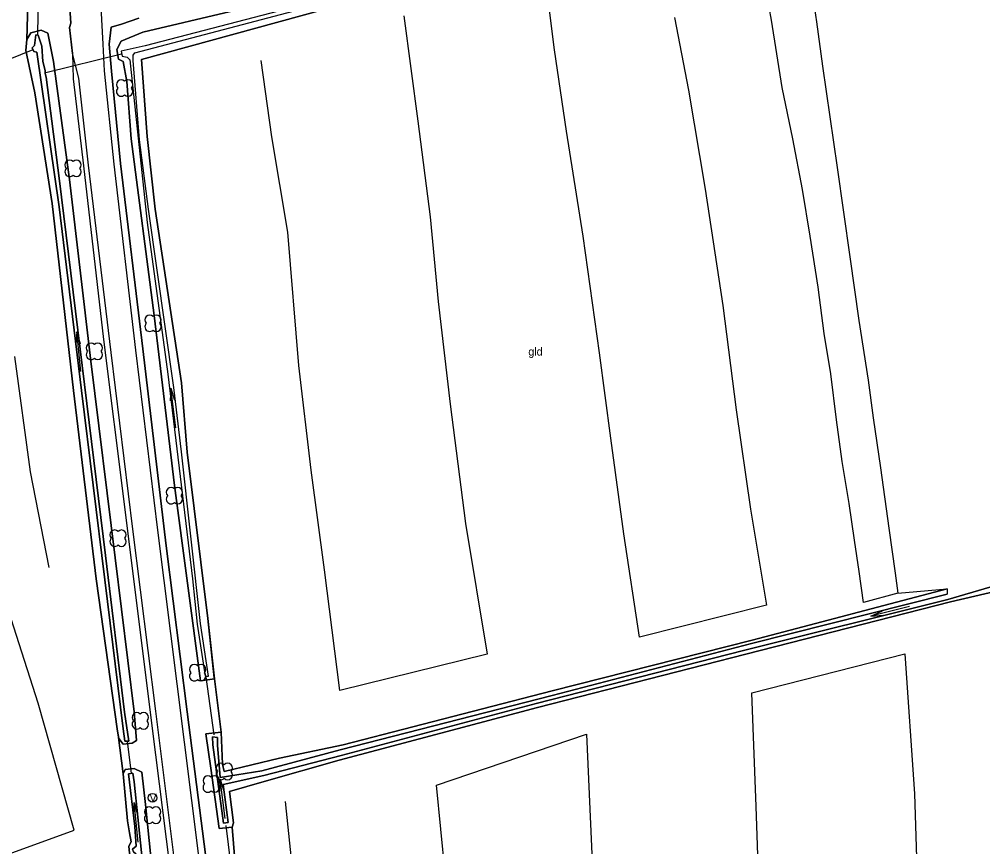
# Model space of a CAD drawing. Extents: x 154825 to 158680, y 370717 to 378075.
# Drawn here: x 157272.6 to 157393.1, y 372826 to 372929.4 of the extents above; entities that cross this region are included whole.
import ezdxf

# ---------------------------------------------------------------- set-up
doc = ezdxf.new("R2010")
doc.units = 0
for name, color, linetype in [('boom', 7, 'Continuous'), ('cultuurscheiding', 7, 'Continuous'), ('duiker lijn', 7, 'Continuous'), ('grasland_productiegrasl(vs)', 7, 'Continuous'), ('greppel - midden sloot', 7, 'Continuous'), ('hoogteverschillijn', 7, 'Continuous'), ('insteek sloot', 7, 'Continuous'), ('kant gesloten verharding', 7, 'Continuous'), ('kant onverhard', 7, 'Continuous'), ('Sloot bodem', 7, 'Continuous'), ('stroomrichting  watergangen', 7, 'Continuous'), ('verkeersbord', 7, 'Continuous'), ('vlak_Grasland', 7, 'Continuous'), ('vlak_Grazige_vegetatie', 7, 'Continuous')]:
    doc.layers.add(name, color=color, linetype=linetype)

msp = doc.modelspace()

# ---------------------------------------------------------------- linework, layer by layer
at = {"layer": 'boom'}
for centre, start, end in [((157285.38, 372921.25), 45, 225), ((157286.23, 372921.25), 315, 135), ((157285.38, 372920.4), 134.7431, 315), ((157286.23, 372920.4), 225, 45), ((157278.95, 372911.22), 45, 225), ((157279.8, 372911.22), 315, 135), ((157278.95, 372910.37), 134.7431, 315), ((157279.8, 372910.37), 225, 45), ((157288.94, 372891.86), 45, 225), ((157289.79, 372891.86), 315, 135), ((157288.94, 372891.01), 134.7431, 315), ((157289.79, 372891.01), 225, 45), ((157281.61, 372888.35), 45, 225), ((157282.46, 372888.35), 315, 135), ((157281.61, 372887.5), 134.7431, 315), ((157282.46, 372887.5), 225, 45), ((157291.62, 372870.3), 45, 225), ((157292.46, 372870.3), 315, 135), ((157291.62, 372869.45), 134.7431, 315), ((157292.46, 372869.45), 225, 45), ((157284.57, 372864.99), 45, 225), ((157285.42, 372864.99), 315, 135), ((157284.57, 372864.14), 134.7431, 315), ((157285.42, 372864.14), 225, 45), ((157294.52, 372848.17), 45, 225), ((157295.36, 372848.17), 315, 135), ((157294.52, 372847.33), 134.7431, 315), ((157295.36, 372847.33), 225, 45), ((157287.34, 372842.16), 45, 225), ((157288.19, 372842.16), 315, 135), ((157287.34, 372841.31), 134.7431, 315), ((157288.19, 372841.31), 225, 45), ((157297.84, 372835.83), 45, 225), ((157298.69, 372835.83), 315, 135), ((157296.21, 372834.26), 45, 225), ((157297.06, 372834.26), 315, 135), ((157297.84, 372834.98), 134.7431, 315), ((157298.69, 372834.98), 225, 45), ((157296.21, 372833.41), 134.7431, 315), ((157297.06, 372833.41), 225, 45), ((157288.88, 372830.37), 45, 225), ((157289.73, 372830.37), 315, 135), ((157288.88, 372829.52), 134.7431, 315), ((157289.73, 372829.52), 225, 45)]:
    msp.add_arc(centre, 0.6, start, end, dxfattribs=at)
at = {"layer": 'cultuurscheiding'}
for points in [[(157273.57, 372926.89), (157273.75, 372932.84)], [(157297.01, 372847.1), (157297.87, 372840.32)], [(157285, 372839.98), (157285.61, 372835.12)], [(157299.27, 372828.45), (157299.79, 372821.84)]]:
    msp.add_lwpolyline(points, dxfattribs=at)
at = {"layer": 'duiker lijn'}
for points in [[(157275.02, 372932.59), (157274.91, 372927.48)], [(157274.34, 372925.61), (157269.46, 372923.65)], [(157285.43, 372925.08), (157275.97, 372922.72)], [(157297, 372840), (157296, 372847.25)], [(157286.11, 372839.14), (157286.62, 372835.21)], [(157298.47, 372828.67), (157299.35, 372821.52)]]:
    msp.add_lwpolyline(points, dxfattribs=at)
at = {"layer": 'greppel - midden sloot'}
for points in [[(157318.67, 372934.04), (157288.4, 372926.09), (157285.36, 372925.43), (157285.52, 372924.8), (157286.11, 372924.7), (157286.47, 372924.34), (157286.84, 372920.82), (157288.65, 372904.01), (157291.2, 372885.05), (157294.29, 372859.48), (157294.89, 372853.8), (157295.87, 372847.3), (157296.29, 372847.31), (157295.28, 372853.91), (157292.92, 372875.35), (157291.97, 372883.39), (157288.79, 372905.69), (157287.69, 372914.37), (157286.86, 372924.28), (157286.9, 372924.96), (157287.1, 372925.24), (157310.82, 372931.47)], [(157274.86, 372925.32), (157274.46, 372925.39), (157274.24, 372925.84), (157274.53, 372926.13), (157274.71, 372927.47), (157275.01, 372927.46), (157275.48, 372926.07), (157275.59, 372924.13), (157275.88, 372923.03), (157275.9, 372922.65), (157276.01, 372922.19), (157277.63, 372909.55), (157283.42, 372862.39), (157285.8, 372842.83), (157286.35, 372839.19), (157285.85, 372839.19), (157285.64, 372840.74), (157283.35, 372859.37), (157280.43, 372883.02), (157277.62, 372906), (157274.86, 372925.32)], [(157388.72, 372856.91), (157363.17, 372850.53), (157337.25, 372843.92), (157312.87, 372837.42), (157303.23, 372834.9), (157298.14, 372833.77), (157298.77, 372829.04), (157298.18, 372828.95), (157296.85, 372838.73), (157296.8, 372839.73), (157297.43, 372839.66), (157297.42, 372838.68), (157297.76, 372834.65), (157302.98, 372835.5), (157312.76, 372838.12), (157339.24, 372844.92), (157364.15, 372851.4), (157388.64, 372857.57)], [(157286.3, 372835.11), (157286.85, 372835.2), (157287.01, 372834.13), (157287.93, 372825.29), (157288.09, 372824.09), (157287.66, 372823.94), (157287.28, 372824.13), (157287.23, 372825.12), (157286.94, 372825.35), (157286.8, 372825.7), (157287.24, 372826.06), (157287.08, 372828.51), (157286.3, 372835.11)]]:
    msp.add_lwpolyline(points, dxfattribs=at)
at = {"layer": 'hoogteverschillijn'}
for points in [[(157371.93, 372931.61), (157372.29, 372929.12), (157373.03, 372923.58), (157374.86, 372910.92), (157376.47, 372899.72), (157377.58, 372891.79), (157378.73, 372884.31), (157379.38, 372879.62), (157380.3, 372873.36), (157381.34, 372865.81), (157382.1, 372860.19), (157382.45, 372857.7), (157378.17, 372856.53), (157377.61, 372860.4), (157377.03, 372864.32), (157376.35, 372868.9), (157375.49, 372874.16), (157374.79, 372879.35), (157374.06, 372885.12), (157373.24, 372890.16), (157372.49, 372895.93), (157371.5, 372902.31), (157370.55, 372908.16), (157369.32, 372914.48), (157368, 372920.92), (157366.67, 372929.3), (157365.48, 372935.71)], [(157354.53, 372929.67), (157356.27, 372920.58), (157358.36, 372908.18), (157360.59, 372893.66), (157362.26, 372880.61), (157364.02, 372868.18), (157366.02, 372856.2), (157350.16, 372852.18), (157348.21, 372865.09), (157346.59, 372877.06), (157345.15, 372887.75), (157343.12, 372902.33), (157341.04, 372915.45), (157339.54, 372925.59), (157338.48, 372933.93)], [(157320.72, 372929.86), (157322.45, 372916.71), (157324, 372904.73), (157325.01, 372894.15), (157326.49, 372881.32), (157328.43, 372866.4), (157331.11, 372850.09), (157312.73, 372845.54), (157310.8, 372860.62), (157309.11, 372873.05), (157307.58, 372886.17), (157306.2, 372902.83), (157304.21, 372914.75), (157302.88, 372924.29)], [(157272.04, 372887.26), (157274, 372872.86), (157276.34, 372860.9)], [(157264.46, 372822.6), (157279.52, 372828.06), (157275, 372843.96), (157269.55, 372860.88)], [(157365.36, 372812.84), (157364.74, 372831.03), (157364.21, 372845.23), (157383.32, 372850.1), (157384.54, 372832.62), (157385.08, 372815.35)], [(157326.96, 372811.68), (157324.79, 372833.68), (157343.55, 372840.05), (157344.51, 372818.54)], [(157305.88, 372831.65), (157306.82, 372822.45)]]:
    msp.add_lwpolyline(points, dxfattribs=at)
at = {"layer": 'insteek sloot'}
for points in [[(157297.04, 372846.99), (157295.31, 372846.72), (157292.04, 372871.14), (157289.51, 372892.39), (157286.62, 372914.5), (157286.1, 372921.67), (157285.63, 372924.14), (157285.03, 372924.45), (157284.84, 372925.67), (157285.38, 372926.7), (157288.07, 372927.8), (157299.03, 372930.41), (157319.21, 372935.81), (157344.59, 372941.96), (157372.7, 372949.2)], [(157297.01, 372847.1), (157296.22, 372854.54), (157293.65, 372875.31), (157292.94, 372883.99), (157289.64, 372905.7), (157288.62, 372914.78), (157287.91, 372924.41), (157310.87, 372930.69), (157339.38, 372937.6), (157365.45, 372944.04), (157374.71, 372946.41)], [(157274.61, 372920.24), (157273.45, 372925.52), (157273.57, 372926.89), (157274.07, 372927.74), (157275.38, 372928.06), (157276.2, 372927.68), (157276.94, 372924.16), (157278.93, 372909.42), (157281.58, 372886.68), (157284.64, 372862.12), (157287, 372842.87), (157287.29, 372839.29), (157286.75, 372838.96), (157285.61, 372838.82), (157285.08, 372839.53), (157284.93, 372840.43), (157282.25, 372859.48), (157279.44, 372883.03), (157276.75, 372906.39), (157274.61, 372920.24)], [(157299.27, 372828.45), (157299.41, 372828.98), (157298.93, 372832.92), (157303.25, 372834.17), (157312.62, 372836.82), (157337.42, 372843.4), (157363.46, 372850.05), (157389.02, 372856.63), (157399.96, 372859.14)], [(157388.63, 372858.23), (157364.23, 372851.83), (157339.25, 372845.47), (157313.11, 372838.73), (157305.15, 372837.07), (157298.27, 372835.41), (157298.06, 372836.3), (157297.87, 372840.32), (157295.97, 372840.13), (157296.6, 372835.82), (157297.64, 372828.27), (157299.27, 372828.45)], [(157286.18, 372829.25), (157285.61, 372835.12), (157285.89, 372835.64), (157286.99, 372835.79), (157287.96, 372835.34), (157288.43, 372831.26), (157289.07, 372824.74), (157288.72, 372823.74), (157287.71, 372823.42), (157286.81, 372823.92), (157286.43, 372825.18), (157286.35, 372826.05), (157286.62, 372826.63), (157286.43, 372827.72), (157286.18, 372829.25)]]:
    msp.add_lwpolyline(points, dxfattribs=at)
at = {"layer": 'kant gesloten verharding'}
for points in [[(157309.45, 372683.01), (157307.81, 372696.98), (157304.61, 372723.02), (157300.48, 372751.36), (157295.86, 372793.73), (157292.97, 372816.93), (157289.7, 372842.93), (157286.83, 372865.69), (157284.12, 372887.77), (157281.31, 372911.18), (157280.08, 372922.05), (157279.28, 372925.15), (157278.91, 372928.41), (157279.1, 372928.93), (157278.95, 372930.8), (157279.23, 372931.22), (157279.08, 372935.46), (157279.01, 372939.65), (157278.96, 372950.66), (157279.4, 372975.64), (157279.77, 372996.09), (157280.14, 373018.34), (157280.49, 373042.16), (157280.55, 373054.05)], [(157312.71, 372683.69), (157310.98, 372696.7), (157309.59, 372707.75), (157308.84, 372712.76), (157307.63, 372722.75), (157304.62, 372748.14), (157302.85, 372762.12), (157300.23, 372783.38), (157299.04, 372793.03), (157296.06, 372817.18), (157292.38, 372846.37), (157289.96, 372865.56), (157287.21, 372888.06), (157284.5, 372911.32), (157283.29, 372922.98), (157283.13, 372926.33), (157282.81, 372932.53)]]:
    msp.add_lwpolyline(points, dxfattribs=at)
at = {"layer": 'kant onverhard'}
for points in [[(157287.57, 372929.57), (157285.41, 372928.83), (157284.14, 372928.46), (157283.86, 372926.31), (157284.17, 372922.95), (157285.28, 372911.39), (157288.08, 372888.25), (157291.02, 372863.61), (157293.62, 372842.88), (157296.91, 372817.23), (157299.06, 372801.5), (157301.94, 372777.18), (157302.78, 372769.87), (157305.82, 372744.51), (157308.26, 372725.88), (157311.3, 372700.25), (157311.8, 372696.63), (157313.43, 372683.38), (157314.9, 372676.59), (157316.73, 372670.52), (157319.22, 372664.68)], [(157279.28, 372925.14), (157279.37, 372921.97), (157280.66, 372911.1), (157283.19, 372889.42), (157285.8, 372868.5), (157289.23, 372841.1), (157292.37, 372816.06), (157299.92, 372751.25), (157303.77, 372722.82), (157306.99, 372696.78), (157309.07, 372682.97), (157312.03, 372669.29), (157315.08, 372660.6)]]:
    msp.add_lwpolyline(points, dxfattribs=at)
at = {"layer": 'Sloot bodem'}
msp.add_lwpolyline([(157393.94, 372858.44), (157388.72, 372856.91)], dxfattribs=at)
at = {"layer": 'stroomrichting  watergangen'}
for p, q in [((157279.83, 372890.34), (157279.71, 372888.77)), ((157280.34, 372885.39), (157279.84, 372890.36)), ((157279.84, 372890.36), (157280.27, 372888.84)), ((157291.57, 372883.31), (157291.5, 372881.73)), ((157292.22, 372878.38), (157291.58, 372883.33)), ((157291.58, 372883.33), (157292.05, 372881.82)), ((157383.92, 372856.03), (157379.08, 372854.83)), ((157379.08, 372854.83), (157380.52, 372855.47)), ((157379.09, 372854.82), (157380.67, 372854.93)), ((157297.74, 372834.44), (157297.66, 372832.87)), ((157298.38, 372829.51), (157297.75, 372834.46)), ((157297.75, 372834.46), (157298.22, 372832.95)), ((157286.98, 372831.5), (157286.87, 372829.93)), ((157287.49, 372826.55), (157287, 372831.52)), ((157287, 372831.52), (157287.42, 372830))]:
    msp.add_line(p, q, dxfattribs=at)
at = {"layer": 'verkeersbord'}
msp.add_circle((157289.3, 372832.12), 0.55, dxfattribs=at)
at = {"layer": 'vlak_Grasland'}
for points in [[(157273.75, 372932.84), (157273.57, 372926.89), (157273.45, 372925.52), (157274.61, 372920.24), (157276.75, 372906.39), (157279.44, 372883.03), (157282.25, 372859.48), (157284.93, 372840.43), (157285, 372839.98), (157285, 372839.98), (157285.61, 372835.12), (157286.18, 372829.25), (157286.43, 372827.72), (157286.62, 372826.63), (157286.35, 372826.05), (157286.43, 372825.18), (157286.81, 372823.92), (157287.68, 372818.18), (157287.88, 372816.38), (157291.17, 372790.32), (157294.25, 372765.18), (157295.37, 372753.02), (157295.55, 372751.15), (157296.48, 372744.59)], [(157371.93, 372931.61), (157372.29, 372929.12), (157373.03, 372923.58), (157374.86, 372910.92), (157376.47, 372899.72), (157377.58, 372891.79), (157378.73, 372884.31), (157379.38, 372879.62), (157380.3, 372873.36), (157381.34, 372865.81), (157382.1, 372860.19), (157382.45, 372857.7), (157388.63, 372858.23), (157364.23, 372851.83), (157339.25, 372845.47), (157313.11, 372838.73), (157305.15, 372837.07), (157298.27, 372835.41), (157298.06, 372836.3), (157297.87, 372840.32), (157297.04, 372846.99), (157296.22, 372854.54), (157293.65, 372875.31), (157292.94, 372883.99), (157289.64, 372905.7), (157288.62, 372914.78), (157287.91, 372924.41), (157310.87, 372930.69)], [(157309.29, 372747.08), (157308.61, 372753.08), (157308.55, 372753.78), (157307.51, 372759.71), (157304.66, 372781.98), (157301.52, 372807.43), (157300.04, 372820.87), (157299.79, 372821.84), (157299.27, 372828.45), (157299.41, 372828.98), (157298.93, 372832.92), (157303.25, 372834.17), (157312.62, 372836.82), (157337.42, 372843.4), (157363.46, 372850.05), (157389.02, 372856.63), (157399.96, 372859.14)]]:
    msp.add_lwpolyline(points, dxfattribs=at)
at = {"layer": 'vlak_Grazige_vegetatie'}
for points in [[(157318.67, 372934.04), (157288.4, 372926.09), (157285.36, 372925.43), (157285.52, 372924.8), (157286.11, 372924.7), (157286.47, 372924.34), (157286.84, 372920.82), (157288.65, 372904.01), (157291.2, 372885.05), (157294.29, 372859.48), (157294.89, 372853.8), (157295.87, 372847.3), (157296.29, 372847.31), (157295.28, 372853.91), (157292.92, 372875.35), (157291.97, 372883.39), (157288.79, 372905.69), (157287.69, 372914.37), (157286.86, 372924.28), (157286.9, 372924.96), (157287.1, 372925.24), (157310.82, 372931.47)], [(157289.07, 372824.74), (157288.43, 372831.26), (157287.96, 372835.34), (157286.99, 372835.79), (157285.89, 372835.64), (157285.61, 372835.12), (157285.01, 372839.98), (157285.08, 372839.53), (157285.61, 372838.82), (157286.75, 372838.96), (157287.29, 372839.29), (157287, 372842.87), (157284.64, 372862.12), (157281.58, 372886.68), (157278.93, 372909.42), (157276.94, 372924.16), (157276.2, 372927.68), (157275.38, 372928.06), (157274.07, 372927.74), (157273.57, 372926.89), (157273.75, 372932.84)], [(157278.95, 372930.8), (157279.1, 372928.93), (157278.91, 372928.41), (157279.28, 372925.14), (157279.37, 372921.97), (157280.66, 372911.1), (157283.19, 372889.42), (157285.8, 372868.5), (157289.23, 372841.1), (157292.37, 372816.06), (157299.92, 372751.25), (157303.77, 372722.82)], [(157310.87, 372930.69), (157287.91, 372924.41), (157288.62, 372914.78), (157289.64, 372905.7), (157292.94, 372883.99), (157293.65, 372875.31), (157296.22, 372854.54), (157297.04, 372846.99), (157295.31, 372846.72), (157292.04, 372871.14), (157289.51, 372892.39), (157286.62, 372914.5), (157286.1, 372921.67), (157285.63, 372924.14), (157285.03, 372924.45), (157284.84, 372925.67), (157285.38, 372926.7), (157288.07, 372927.8), (157299.03, 372930.41)], [(157299.03, 372930.41), (157288.07, 372927.8), (157285.38, 372926.7), (157284.84, 372925.67), (157285.03, 372924.45), (157285.63, 372924.14), (157286.1, 372921.67), (157286.62, 372914.5), (157289.51, 372892.39), (157292.04, 372871.14), (157295.31, 372846.72), (157297.04, 372846.99), (157297.87, 372840.32), (157295.97, 372840.13), (157296.6, 372835.82), (157297.64, 372828.27), (157299.27, 372828.45), (157299.79, 372821.84)], [(157305.82, 372744.51), (157302.78, 372769.87), (157301.94, 372777.18), (157299.06, 372801.5), (157296.91, 372817.23), (157293.62, 372842.88), (157291.02, 372863.61), (157288.08, 372888.25), (157285.28, 372911.39), (157284.17, 372922.95), (157283.86, 372926.31), (157284.14, 372928.46), (157285.41, 372928.83), (157287.57, 372929.57)], [(157399.96, 372859.14), (157389.02, 372856.63), (157363.46, 372850.05), (157337.42, 372843.4), (157312.62, 372836.82), (157303.25, 372834.17), (157298.93, 372832.92), (157299.41, 372828.98), (157299.27, 372828.45), (157297.64, 372828.27), (157296.6, 372835.82), (157295.97, 372840.13), (157297.87, 372840.32), (157298.06, 372836.3), (157298.27, 372835.41), (157305.15, 372837.07), (157313.11, 372838.73), (157339.25, 372845.47), (157364.23, 372851.83), (157388.63, 372858.23), (157388.64, 372857.57), (157364.15, 372851.4), (157339.24, 372844.92), (157312.76, 372838.12), (157302.98, 372835.5), (157297.76, 372834.65), (157297.42, 372838.68), (157297.43, 372839.66), (157296.8, 372839.73), (157296.85, 372838.73), (157298.18, 372828.95), (157298.77, 372829.04), (157298.14, 372833.77), (157303.23, 372834.9), (157312.87, 372837.42), (157337.25, 372843.92), (157363.17, 372850.53), (157388.72, 372856.91), (157393.94, 372858.44)]]:
    msp.add_lwpolyline(points, dxfattribs=at)
for points in [[(157276.2, 372927.68), (157276.94, 372924.16), (157278.93, 372909.42), (157281.58, 372886.68), (157284.64, 372862.12), (157287, 372842.87), (157287.29, 372839.29), (157286.75, 372838.96), (157285.61, 372838.82), (157285.08, 372839.53), (157285, 372839.98), (157284.93, 372840.43), (157282.25, 372859.48), (157279.44, 372883.03), (157276.75, 372906.39), (157274.61, 372920.24), (157273.45, 372925.52), (157273.57, 372926.89), (157274.07, 372927.74), (157275.38, 372928.06)], [(157285.64, 372840.74), (157285.85, 372839.19), (157286.35, 372839.19), (157285.8, 372842.83), (157283.42, 372862.39), (157277.63, 372909.55), (157276.01, 372922.19), (157275.9, 372922.65), (157275.88, 372923.03), (157275.59, 372924.13), (157275.48, 372926.07), (157275.01, 372927.46), (157274.71, 372927.47), (157274.53, 372926.13), (157274.24, 372925.84), (157274.46, 372925.39), (157274.86, 372925.32), (157277.62, 372906), (157280.43, 372883.02), (157283.35, 372859.37)], [(157287.96, 372835.34), (157288.43, 372831.26), (157289.07, 372824.74), (157288.72, 372823.74), (157287.71, 372823.42), (157286.81, 372823.92), (157286.43, 372825.18), (157286.35, 372826.05), (157286.62, 372826.63), (157286.43, 372827.72), (157286.18, 372829.25), (157285.61, 372835.12), (157285.89, 372835.64), (157286.99, 372835.79)], [(157287.28, 372824.13), (157287.66, 372823.94), (157288.09, 372824.09), (157287.93, 372825.29), (157287.01, 372834.13), (157286.85, 372835.2), (157286.3, 372835.11), (157287.08, 372828.51), (157287.24, 372826.06), (157286.8, 372825.7), (157286.94, 372825.35), (157287.23, 372825.12)]]:
    msp.add_lwpolyline(points, close=True, dxfattribs=at)

# ---------------------------------------------------------------- texts
at = {"layer": 'grasland_productiegrasl(vs)'}
msp.add_text('gld', height=1, dxfattribs=at).set_placement((157336.27, 372887.39))
at = {"layer": 'verkeersbord'}
msp.add_text('V', height=1, dxfattribs=at).set_placement((157288.92, 372831.62))

doc.saveas('drawing.dxf')
